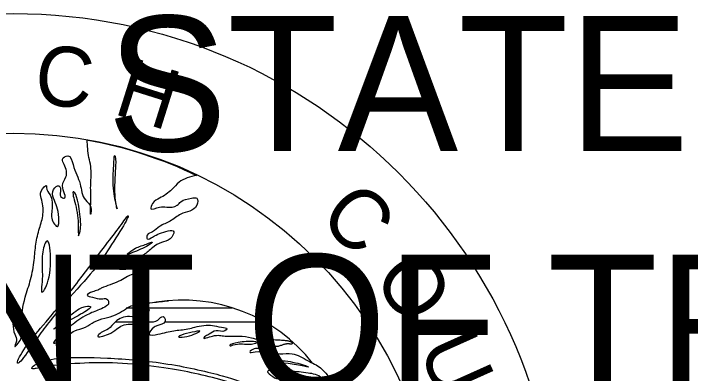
# Model space of a CAD drawing. Extents: x -0.7 to 16, y -0.9 to 9.7.
# Drawn here: x 9.071 to 9.4218, y -0.2602 to -0.0737 of the extents above; entities that cross this region are included whole.
import ezdxf

# ---------------------------------------------------------------- set-up
doc = ezdxf.new("R2010")
doc.units = 0
doc.layers.add('Default', color=7, linetype='Continuous')
doc.layers.add('TextMisc', color=7, linetype='Continuous')

msp = doc.modelspace()

# ---------------------------------------------------------------- linework, layer by layer
at = {"layer": 'Default'}
for p, q in [((9.129340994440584, -0.2261339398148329), (9.184269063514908, -0.22613330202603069)), ((9.123834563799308, -0.2334531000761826), (9.141228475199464, -0.23344832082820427)), ((9.149467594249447, -0.23346653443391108), (9.20164932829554, -0.23345219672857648))]:
    msp.add_line(p, q, dxfattribs=at)
for radius in [0.28240568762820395, 0.2204114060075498]:
    msp.add_circle((9.070985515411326, -0.3561222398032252), radius, dxfattribs=at)
for centre, radius, start, end in [((9.070271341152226, -0.35626193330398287), 0.2204114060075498, 64.23515824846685, 79.6893776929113), ((9.158541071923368, -0.3082713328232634), 0.08611740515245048, 38.42000269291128, 99.14313602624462)]:
    msp.add_arc(centre, radius, start, end, dxfattribs=at)
for points in [[(8.99749953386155, -0.19684500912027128), (8.994757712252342, -0.1913385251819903), (8.99018031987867, -0.18676123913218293), (8.983776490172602, -0.1812822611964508), (8.980100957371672, -0.1794329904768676), (8.98011009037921, -0.1776021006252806), (8.983771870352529, -0.17762036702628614), (8.991086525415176, -0.17944201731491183), (9.00025038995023, -0.1821883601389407), (9.003907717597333, -0.18309918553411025), (9.007583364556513, -0.1849255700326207), (9.010325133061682, -0.1858547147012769), (9.011236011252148, -0.18677472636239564), (9.013973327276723, -0.18859642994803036), (9.012156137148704, -0.18584096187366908), (9.010320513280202, -0.18219282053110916), (9.007564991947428, -0.17943267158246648), (9.005743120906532, -0.1776155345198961), (9.006667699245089, -0.17578921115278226), (9.00849413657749, -0.176690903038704), (9.015804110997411, -0.17945088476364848), (9.023146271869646, -0.18493454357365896), (9.027719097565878, -0.1904272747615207), (9.030470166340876, -0.19407998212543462), (9.034118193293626, -0.19226724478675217), (9.032291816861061, -0.18676532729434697), (9.030460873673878, -0.18217885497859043), (9.027723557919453, -0.1803571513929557), (9.026794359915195, -0.17852158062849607), (9.028629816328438, -0.17761526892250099), (9.035042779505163, -0.18126335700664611), (9.041446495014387, -0.18676522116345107), (9.046930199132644, -0.1931779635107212), (9.049681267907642, -0.19683067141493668), (9.05335240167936, -0.20414983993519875), (9.054254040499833, -0.19774606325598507), (9.053343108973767, -0.19224871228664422), (9.051507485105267, -0.18860057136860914), (9.049685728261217, -0.18676054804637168), (9.0506103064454, -0.18493422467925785), (9.05426763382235, -0.1858450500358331), (9.058845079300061, -0.19499967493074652), (9.063427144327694, -0.20781619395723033), (9.06615526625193, -0.21606901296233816), (9.068920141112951, -0.22613006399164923), (9.070732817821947, -0.23437831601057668), (9.071666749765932, -0.23985289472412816), (9.072563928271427, -0.24351924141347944), (9.071657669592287, -0.24626112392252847), (9.073497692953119, -0.24443936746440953), (9.075310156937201, -0.23437826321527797), (9.077141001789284, -0.2206324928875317), (9.079887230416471, -0.21149151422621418), (9.081722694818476, -0.20140763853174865), (9.082633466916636, -0.19317297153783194), (9.08448257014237, -0.18494298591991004), (9.0863043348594, -0.1776054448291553), (9.085384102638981, -0.1693845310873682), (9.085379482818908, -0.16572263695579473), (9.088139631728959, -0.1629671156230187), (9.08813506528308, -0.16388256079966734), (9.089970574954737, -0.16755358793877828), (9.090890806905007, -0.17577450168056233), (9.091797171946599, -0.18218729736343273), (9.093618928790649, -0.18402732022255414), (9.094534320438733, -0.17945454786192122), (9.091792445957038, -0.16937072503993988), (9.091792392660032, -0.16479338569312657), (9.094547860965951, -0.16297619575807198), (9.095454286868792, -0.16478876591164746), (9.095458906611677, -0.16845066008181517), (9.097285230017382, -0.169375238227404), (9.09637886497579, -0.1629624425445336), (9.098209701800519, -0.15839423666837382), (9.097280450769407, -0.15198132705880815), (9.096378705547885, -0.14923042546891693), (9.099111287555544, -0.14741312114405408), (9.101857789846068, -0.15198127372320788), (9.10553810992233, -0.16204689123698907), (9.108266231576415, -0.1702997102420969), (9.111017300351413, -0.17395241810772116), (9.111021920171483, -0.17761431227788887), (9.11103100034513, -0.17120608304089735), (9.11103089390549, -0.16205140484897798), (9.111030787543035, -0.15289672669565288), (9.110115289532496, -0.1483148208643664), (9.109199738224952, -0.13915557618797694)], [(9.165958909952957, -0.15747342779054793), (9.156785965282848, -0.161135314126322), (9.153128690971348, -0.16480182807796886), (9.146720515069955, -0.16937008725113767), (9.14306780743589, -0.17212115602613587), (9.142138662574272, -0.17486292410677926), (9.146720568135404, -0.17394742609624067), (9.150382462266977, -0.17394280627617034), (9.155879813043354, -0.1730318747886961), (9.157719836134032, -0.17121011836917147), (9.16319886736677, -0.16938362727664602), (9.165945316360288, -0.16937444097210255), (9.165949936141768, -0.1730363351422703), (9.157710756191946, -0.17761834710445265), (9.152222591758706, -0.181275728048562), (9.146716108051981, -0.18401754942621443), (9.143063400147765, -0.18676861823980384), (9.140307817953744, -0.1886086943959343), (9.140321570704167, -0.19043969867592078), (9.143072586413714, -0.189515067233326), (9.146720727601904, -0.18767944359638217), (9.154048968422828, -0.18677764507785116), (9.152222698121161, -0.1904304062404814), (9.147636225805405, -0.19226134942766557), (9.143068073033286, -0.19500785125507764), (9.138495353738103, -0.19866979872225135), (9.13482432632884, -0.20050530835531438), (9.130237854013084, -0.20233625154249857), (9.126594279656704, -0.20325643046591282), (9.123838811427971, -0.2050736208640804), (9.130242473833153, -0.20599814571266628), (9.132993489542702, -0.20507351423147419), (9.135748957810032, -0.20325632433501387), (9.137561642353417, -0.20232701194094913), (9.13756626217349, -0.20598890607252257), (9.132998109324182, -0.20873540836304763), (9.125678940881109, -0.21240654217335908), (9.116505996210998, -0.2160684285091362), (9.11469342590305, -0.21697485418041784), (9.111942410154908, -0.21789948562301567), (9.109186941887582, -0.219716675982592), (9.111928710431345, -0.2206458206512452), (9.116524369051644, -0.2215613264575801), (9.119270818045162, -0.22155214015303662), (9.120172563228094, -0.22430304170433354), (9.119252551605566, -0.22521392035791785), (9.115604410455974, -0.22704954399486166), (9.109182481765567, -0.22978679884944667), (9.100961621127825, -0.23528436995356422), (9.094548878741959, -0.24076807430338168), (9.09180704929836, -0.2444391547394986), (9.096370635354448, -0.24260809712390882), (9.102778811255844, -0.2380398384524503), (9.108280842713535, -0.2361905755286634), (9.112848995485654, -0.2334440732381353), (9.123829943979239, -0.22979120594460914), (9.132069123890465, -0.22520919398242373), (9.143063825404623, -0.2233873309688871), (9.151307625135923, -0.22246721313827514)], [(9.141237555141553, -0.22704009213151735), (9.14030829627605, -0.22980474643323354), (9.131172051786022, -0.23069752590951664), (9.123834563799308, -0.2334531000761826), (9.12017728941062, -0.2371196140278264), (9.116506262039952, -0.2389551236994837), (9.114689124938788, -0.24077699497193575), (9.120186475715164, -0.23986606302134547), (9.1275102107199, -0.23527948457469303), (9.135731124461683, -0.23435925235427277), (9.141228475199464, -0.23344832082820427), (9.145810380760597, -0.23253282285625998), (9.148565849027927, -0.23071563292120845), (9.149476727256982, -0.23163564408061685), (9.149467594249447, -0.23346653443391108), (9.14581956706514, -0.23527927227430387), (9.14398399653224, -0.23620846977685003), (9.141242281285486, -0.23985666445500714), (9.145819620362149, -0.23985661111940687), (9.15404498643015, -0.23804382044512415), (9.161373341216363, -0.23711913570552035), (9.165039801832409, -0.23619907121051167), (9.169621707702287, -0.23528357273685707), (9.174199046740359, -0.23528351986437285), (9.178771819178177, -0.23619891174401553), (9.181513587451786, -0.23712805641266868), (9.180593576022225, -0.23803893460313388), (9.176016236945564, -0.23803898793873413), (9.172368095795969, -0.23987461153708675), (9.170532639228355, -0.24078092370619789), (9.169612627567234, -0.2416918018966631), (9.174194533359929, -0.2407763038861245), (9.180602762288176, -0.24078538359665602), (9.187926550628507, -0.24077614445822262), (9.194330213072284, -0.24170066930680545), (9.197987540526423, -0.2426114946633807), (9.201649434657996, -0.2426068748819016)], [(9.208062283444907, -0.24627784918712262), (9.204400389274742, -0.2462824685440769), (9.199818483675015, -0.24719796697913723), (9.19707214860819, -0.24718426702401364), (9.194321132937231, -0.24810889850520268), (9.193401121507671, -0.24901977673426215), (9.196147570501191, -0.24901059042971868), (9.20255579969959, -0.24901967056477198), (9.208982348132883, -0.24994430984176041), (9.215390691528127, -0.24993050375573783), (9.223611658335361, -0.2535876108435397), (9.23002450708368, -0.2572585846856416), (9.232780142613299, -0.2599958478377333), (9.234615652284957, -0.2636668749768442), (9.233695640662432, -0.26457775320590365), (9.230935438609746, -0.26275593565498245), (9.223625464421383, -0.25999595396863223), (9.214475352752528, -0.2590806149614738), (9.208067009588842, -0.25909442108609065), (9.202574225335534, -0.2590899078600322), (9.205306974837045, -0.2618270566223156), (9.212644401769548, -0.26367170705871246), (9.219043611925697, -0.26548879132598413), (9.2272873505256, -0.2691688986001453), (9.235522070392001, -0.2746570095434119), (9.241019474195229, -0.27832341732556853), (9.243770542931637, -0.281976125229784), (9.247414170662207, -0.2856332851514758), (9.24742792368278, -0.28746428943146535), (9.244672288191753, -0.2847270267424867), (9.236442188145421, -0.2829008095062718), (9.230029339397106, -0.2792298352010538), (9.22637657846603, -0.27740356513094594), (9.224541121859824, -0.2783098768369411), (9.231869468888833, -0.2865627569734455), (9.23644229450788, -0.2920554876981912), (9.2428369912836, -0.29936535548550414), (9.246503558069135, -0.3075999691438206), (9.24926369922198, -0.31402201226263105), (9.250179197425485, -0.3186039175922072), (9.250165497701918, -0.32135025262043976), (9.249250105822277, -0.325923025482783), (9.24741464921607, -0.3268293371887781), (9.245601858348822, -0.3186039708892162), (9.236442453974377, -0.3057875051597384), (9.230940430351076, -0.298459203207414), (9.221790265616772, -0.29296652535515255), (9.221785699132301, -0.2938819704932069), (9.225443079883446, -0.2993701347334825), (9.230954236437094, -0.3048675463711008), (9.233700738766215, -0.30943569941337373), (9.235513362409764, -0.3131066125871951), (9.235527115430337, -0.3149376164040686), (9.234597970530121, -0.317679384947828), (9.229114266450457, -0.3112666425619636), (9.223612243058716, -0.30393834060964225), (9.216302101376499, -0.2966239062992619), (9.210804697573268, -0.2929574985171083), (9.207151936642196, -0.2911312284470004), (9.208982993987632, -0.2956948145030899), (9.208983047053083, -0.30027215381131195), (9.211715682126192, -0.3030321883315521), (9.209889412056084, -0.30668494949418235), (9.208058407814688, -0.30669870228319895), (9.201645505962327, -0.2984503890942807), (9.194335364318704, -0.2911359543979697), (9.189739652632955, -0.28564310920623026), (9.184246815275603, -0.28106125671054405), (9.180589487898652, -0.2801504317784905), (9.17785228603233, -0.27830584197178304), (9.176941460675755, -0.2819631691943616), (9.179687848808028, -0.2865542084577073), (9.18150058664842, -0.2902022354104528), (9.183336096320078, -0.29387326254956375), (9.182429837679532, -0.29661514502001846), (9.180598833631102, -0.2966288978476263), (9.177852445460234, -0.29203785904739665), (9.172364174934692, -0.28654056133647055), (9.162293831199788, -0.27740430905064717), (9.157711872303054, -0.27374246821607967), (9.154054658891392, -0.2728087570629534), (9.151312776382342, -0.27190249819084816), (9.152214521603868, -0.2746533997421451), (9.156791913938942, -0.27923068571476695), (9.159547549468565, -0.28196794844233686), (9.161360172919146, -0.2856388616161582), (9.16136935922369, -0.2883853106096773), (9.156796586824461, -0.2874699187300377), (9.15128999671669, -0.281057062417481), (9.145810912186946, -0.2783062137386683), (9.137571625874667, -0.2737335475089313)], [(9.208062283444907, -0.24627784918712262), (9.204400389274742, -0.2462824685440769), (9.199818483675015, -0.24719796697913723), (9.19707214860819, -0.24718426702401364), (9.194321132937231, -0.24810889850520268), (9.193401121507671, -0.24901977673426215), (9.196147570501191, -0.24901059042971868), (9.20255579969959, -0.24901967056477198), (9.208982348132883, -0.24994430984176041), (9.215390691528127, -0.24993050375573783), (9.223611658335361, -0.2535876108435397), (9.23002450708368, -0.2572585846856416), (9.232780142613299, -0.2599958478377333), (9.234615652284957, -0.2636668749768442), (9.233695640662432, -0.26457775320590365), (9.230935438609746, -0.26275593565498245), (9.223625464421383, -0.25999595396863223), (9.214475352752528, -0.2590806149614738), (9.208067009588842, -0.25909442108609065), (9.202574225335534, -0.2590899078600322), (9.205306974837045, -0.2618270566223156), (9.212644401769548, -0.26367170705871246), (9.219043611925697, -0.26548879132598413), (9.2272873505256, -0.2691688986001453), (9.235522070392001, -0.2746570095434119), (9.241019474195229, -0.27832341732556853), (9.243770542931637, -0.281976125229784), (9.247414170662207, -0.2856332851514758), (9.24742792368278, -0.28746428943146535), (9.244672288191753, -0.2847270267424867), (9.236442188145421, -0.2829008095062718), (9.230029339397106, -0.2792298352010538), (9.22637657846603, -0.27740356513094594), (9.224541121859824, -0.2783098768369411), (9.231869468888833, -0.2865627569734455), (9.23644229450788, -0.2920554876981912), (9.2428369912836, -0.29936535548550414), (9.246503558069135, -0.3075999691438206), (9.24926369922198, -0.31402201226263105), (9.250179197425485, -0.3186039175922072), (9.250165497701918, -0.32135025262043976), (9.249250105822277, -0.325923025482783), (9.24741464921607, -0.3268293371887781), (9.245601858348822, -0.3186039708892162), (9.236442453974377, -0.3057875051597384), (9.230940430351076, -0.298459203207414), (9.221790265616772, -0.29296652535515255), (9.221785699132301, -0.2938819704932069), (9.225443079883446, -0.2993701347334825), (9.230954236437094, -0.3048675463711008), (9.233700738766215, -0.30943569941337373), (9.235513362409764, -0.3131066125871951), (9.235527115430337, -0.3149376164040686), (9.234597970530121, -0.317679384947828), (9.229114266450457, -0.3112666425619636), (9.223612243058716, -0.30393834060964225), (9.216302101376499, -0.2966239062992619), (9.210804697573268, -0.2929574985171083), (9.207151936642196, -0.2911312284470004), (9.208982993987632, -0.2956948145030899), (9.208983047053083, -0.30027215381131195), (9.211715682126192, -0.3030321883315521), (9.209889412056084, -0.30668494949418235), (9.208058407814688, -0.30669870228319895), (9.201645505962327, -0.2984503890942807), (9.194335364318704, -0.2911359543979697), (9.189739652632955, -0.28564310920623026), (9.184246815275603, -0.28106125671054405), (9.180589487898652, -0.2801504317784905), (9.17785228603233, -0.27830584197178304), (9.176941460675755, -0.2819631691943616), (9.179687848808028, -0.2865542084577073), (9.18150058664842, -0.2902022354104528), (9.183336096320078, -0.29387326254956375), (9.182429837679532, -0.29661514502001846), (9.180598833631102, -0.2966288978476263), (9.177852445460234, -0.29203785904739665), (9.172364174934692, -0.28654056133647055), (9.162293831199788, -0.27740430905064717), (9.157711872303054, -0.27374246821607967), (9.154054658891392, -0.2728087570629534), (9.151312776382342, -0.27190249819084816), (9.152214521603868, -0.2746533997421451), (9.156791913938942, -0.27923068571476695), (9.159547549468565, -0.28196794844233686), (9.161360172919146, -0.2856388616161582), (9.16136935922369, -0.2883853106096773), (9.156796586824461, -0.2874699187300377), (9.15128999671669, -0.281057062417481), (9.145810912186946, -0.2783062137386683), (9.137571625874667, -0.2737335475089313)]]:
    msp.add_spline(points, degree=3, dxfattribs=at)
for points, degree in [([(9.124451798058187, -0.1739507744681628), (9.124756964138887, -0.1754780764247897), (9.124744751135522, -0.1748677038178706), (9.122002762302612, -0.16480676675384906), (9.122918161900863, -0.15105642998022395), (9.122918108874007, -0.14647909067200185), (9.124762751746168, -0.14831922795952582), (9.12291375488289, -0.16570389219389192), (9.124146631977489, -0.17242347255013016), (9.124451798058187, -0.1739507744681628)], 3), ([(9.10492201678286, -0.18843980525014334), (9.10461687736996, -0.18920117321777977), (9.104604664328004, -0.18859080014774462), (9.104618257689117, -0.17668978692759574), (9.10094250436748, -0.16570872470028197), (9.102773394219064, -0.16571785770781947), (9.104622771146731, -0.17119700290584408), (9.106435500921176, -0.18402259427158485), (9.105227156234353, -0.187678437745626), (9.10492201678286, -0.18843980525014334)], 3), ([(9.073334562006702, -0.2534368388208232), (9.072573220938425, -0.2554203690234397), (9.07440411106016, -0.2554295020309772), (9.08356319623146, -0.2407819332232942), (9.098210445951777, -0.22247698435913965), (9.113764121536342, -0.20598460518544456), (9.120176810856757, -0.19592356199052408), (9.130255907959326, -0.18036511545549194), (9.131166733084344, -0.17670778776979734), (9.125678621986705, -0.18494250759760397), (9.118355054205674, -0.19408353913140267), (9.105520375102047, -0.21148206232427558), (9.08813129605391, -0.23345809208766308), (9.078972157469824, -0.24352832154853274), (9.07409590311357, -0.25145330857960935), (9.073334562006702, -0.2534368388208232)], 3), ([(9.085536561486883, -0.21528837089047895), (9.085689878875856, -0.2136107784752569), (9.086300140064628, -0.21056226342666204), (9.085389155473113, -0.20048757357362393), (9.087219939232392, -0.19134202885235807), (9.089970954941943, -0.19041739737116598), (9.090882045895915, -0.2096467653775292), (9.08538023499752, -0.22062781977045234), (9.085383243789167, -0.21696596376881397), (9.085536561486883, -0.21528837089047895)], 3), ([(9.130255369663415, -0.19806034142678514), (9.129645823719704, -0.19867142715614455), (9.130256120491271, -0.19867447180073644), (9.141241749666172, -0.19408327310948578), (9.143978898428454, -0.19135052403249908), (9.140307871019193, -0.19318603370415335), (9.133913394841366, -0.19500795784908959), (9.1308649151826, -0.19744925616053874), (9.130255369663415, -0.19806034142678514)], 3), ([(9.093168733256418, -0.23604271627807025), (9.09118446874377, -0.2377226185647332), (9.091797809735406, -0.23711536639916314), (9.105520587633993, -0.22979141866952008), (9.112844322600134, -0.22520484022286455), (9.108266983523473, -0.22520489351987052), (9.103703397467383, -0.22703595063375), (9.09515299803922, -0.2343628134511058), (9.093168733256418, -0.23604271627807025)], 3), ([(9.157560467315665, -0.241391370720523), (9.156492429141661, -0.24138985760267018), (9.155885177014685, -0.24077651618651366), (9.162279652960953, -0.23895459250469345), (9.167777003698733, -0.23804366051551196), (9.167777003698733, -0.23804366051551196), (9.166856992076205, -0.23895453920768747), (9.162293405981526, -0.24078559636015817), (9.158628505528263, -0.24139288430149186), (9.157560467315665, -0.241391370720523)], 3), ([(9.183648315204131, -0.24581276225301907), (9.183041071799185, -0.24596231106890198), (9.182433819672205, -0.24534897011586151), (9.188828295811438, -0.24352704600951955), (9.198898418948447, -0.2435315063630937), (9.195250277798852, -0.24536712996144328), (9.18607728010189, -0.24445167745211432), (9.18425555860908, -0.24566321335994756), (9.183648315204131, -0.24581276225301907)], 3), ([(9.201649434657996, -0.2426068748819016), (9.208973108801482, -0.24262052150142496), (9.215376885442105, -0.2435221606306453), (9.215390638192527, -0.24535316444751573), (9.212625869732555, -0.2444467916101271), (9.208062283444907, -0.24627784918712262)], 2), ([(9.08065600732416, -0.2569559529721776), (9.080199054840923, -0.25756398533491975), (9.080821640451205, -0.25816214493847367), (9.08721611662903, -0.2563402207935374), (9.108281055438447, -0.25449993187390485), (9.126590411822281, -0.25449971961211), (9.150378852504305, -0.2572503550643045), (9.165035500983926, -0.26000121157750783), (9.179687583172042, -0.2636675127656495), (9.194335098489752, -0.26824925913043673), (9.199814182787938, -0.2710001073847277), (9.202556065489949, -0.2719063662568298), (9.194321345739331, -0.2664182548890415), (9.182420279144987, -0.26182732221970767), (9.151307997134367, -0.25450858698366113), (9.118341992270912, -0.2517579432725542), (9.09362429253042, -0.25177196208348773), (9.083563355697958, -0.25451395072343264), (9.081112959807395, -0.2563479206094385), (9.08065600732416, -0.2569559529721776)], 3), ([(9.202101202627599, -0.2537435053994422), (9.201640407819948, -0.2535924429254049), (9.203471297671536, -0.25360157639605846), (9.214456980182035, -0.2535877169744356), (9.225447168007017, -0.2572586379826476), (9.22270528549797, -0.25635237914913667), (9.212644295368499, -0.2545170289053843), (9.206236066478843, -0.25450794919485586), (9.20256199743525, -0.25389456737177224), (9.202101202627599, -0.2537435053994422)], 3)]:
    msp.add_open_spline(points, degree=degree, dxfattribs=at)

# ---------------------------------------------------------------- texts
for s, height, rotation, p in [('C', 0.03099552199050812, 353.22679158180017, (9.080801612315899, -0.11994929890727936)), ('H', 0.030995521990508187, 342.4878499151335, (9.122016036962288, -0.1254417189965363)), ('C', 0.03099552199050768, 315.6404999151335, (9.228211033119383, -0.18035024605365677)), ('O', 0.03099552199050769, 304.9015582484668, (9.25657713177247, -0.21056486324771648)), ('U', 0.03099552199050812, 294.1626165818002, (9.280379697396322, -0.24718787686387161))]:
    msp.add_text(s, height=height, rotation=rotation, dxfattribs=at).set_placement(p)
at = {"layer": 'TextMisc'}
for s, p in [('STATE OF FLORIDA', (9.119371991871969, -0.14500000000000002)), ('DEPARTMENT OF TRANSPORTATION', (8.52074908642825, -0.26859318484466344))]:
    msp.add_text(s, height=0.07000000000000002, dxfattribs=at).set_placement(p)

doc.saveas('drawing.dxf')
